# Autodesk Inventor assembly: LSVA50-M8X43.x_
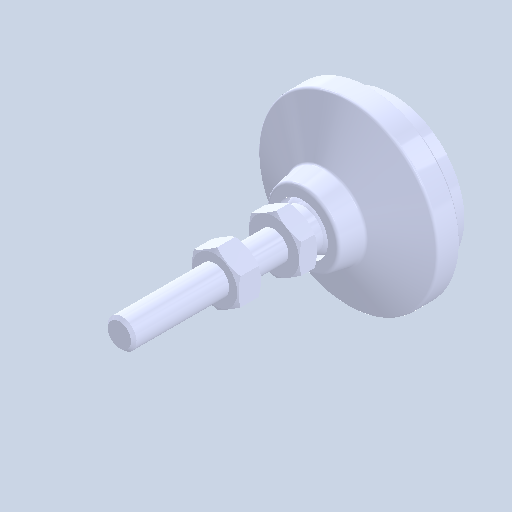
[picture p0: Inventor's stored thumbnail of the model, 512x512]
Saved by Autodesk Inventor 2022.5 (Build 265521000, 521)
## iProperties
Created: 2024-08
Part Number: LSVA50-M8X43.x_
Document SubType Name: Assembly
Designer: ImaoCorp
Author: ImaoCorp
Sending System: SOLIDWORKS 2022-2022290
MC: AMD64
MC_MODEL: Intel64 Family 6 Model 60 Stepping 3, GenuineIntel
OS: Windows_NT
FRU: Parasolid Version 33.1, build 260,  4-25-2022
FORMAT: text
GUISE: transmit
KEY: FILELSVA50-M8X43.x_t
DATE: Fri Aug 23 16:08:49 2024
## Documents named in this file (4)
- X:\14_SW2022-Inv2022\06_2024-10新製品(SME)\ELS_データ\l\lsva50-m8x43\LSVA50-M8X43.x_.iam
- X:\14_SW2022-Inv2022\06_2024-10新製品(SME)\ELS_データ\l\lsva50-m8x43\LSVA50-M8X43_01.ipt
- X:\14_SW2022-Inv2022\06_2024-10新製品(SME)\ELS_データ\l\lsva50-m8x43\LSVA50-M8X43_02.ipt
- X:\14_SW2022-Inv2022\06_2024-10新製品(SME)\ELS_データ\l\lsva50-m8x43\LSVA50-M8X43_03.ipt
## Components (3 placed, 3 different names)
1. LSVA50-M8X43_01
2. LSVA50-M8X43_02
3. LSVA50-M8X43_03
